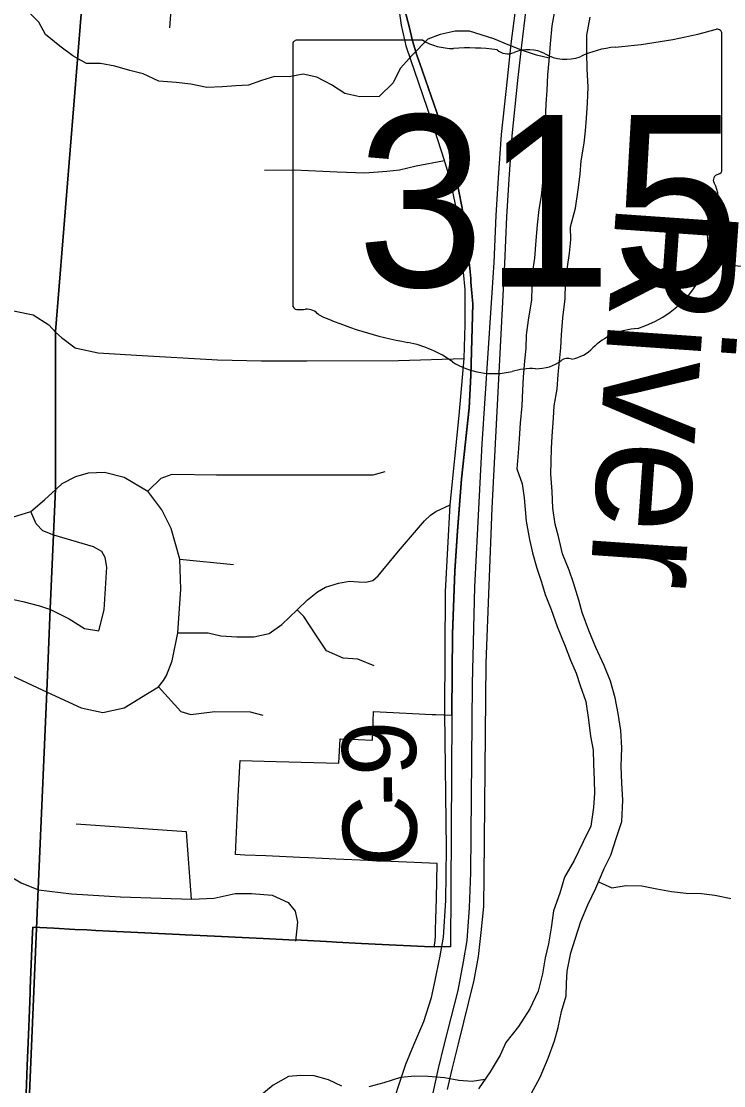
# Model space of a CAD drawing. Extents: x 0 to 34, y 0 to 22.
# Drawn here: x 17.773 to 18.313, y 5.441 to 6.258 of the extents above; entities that cross this region are included whole.
import ezdxf

# ---------------------------------------------------------------- set-up
doc = ezdxf.new("R2010")
doc.units = 0
for name, color, linetype in [('GM_X_City_Street', 7, 'Continuous'), ('GM_X_Corporation', 7, 'Continuous'), ('GM_X_County_Road', 7, 'Continuous'), ('GM_X_County_Road_Text', 7, 'Continuous'), ('GM_X_Major_River', 7, 'Continuous'), ('GM_X_Major_River_Text', 7, 'Continuous'), ('GM_X_Minor_River', 7, 'Continuous'), ('GM_X_State_Location', 7, 'Continuous'), ('GM_X_State_Route', 7, 'Continuous'), ('GM_X_State_Shield', 7, 'Continuous')]:
    doc.layers.add(name, color=color, linetype=linetype)

msp = doc.modelspace()

# ---------------------------------------------------------------- linework, layer by layer
at = {"layer": 'GM_X_City_Street'}
msp.add_line((17.89471, 5.84522), (17.93593, 5.84123), dxfattribs=at)
for points in [[(17.88709, 6.2533), (17.88947, 6.28453), (17.88813, 6.29703), (17.88332, 6.31817)], [(17.95974, 6.14412), (17.98255, 6.14437), (18.01567, 6.14269), (18.03679, 6.14196), (18.05383, 6.14317), (18.06343, 6.14437), (18.07639, 6.14749), (18.09811, 6.15159)], [(18.30145, 6.07219), (18.37497, 6.06686), (18.37576, 6.06678), (18.3924, 6.06505), (18.41174, 6.06059), (18.42842, 6.05801), (18.44511, 6.05278), (18.45076, 6.05245), (18.50915, 6.04895), (18.56071, 6.04583), (18.63152, 6.04155), (18.6683, 6.03945), (18.67549, 6.04139), (18.68078, 6.04406)], [(17.60122, 5.92209), (17.63267, 5.9094), (17.63905, 5.90785), (17.6524, 5.90631), (17.66246, 5.90573), (17.67, 5.90399), (17.68083, 5.9007), (17.69169, 5.89479), (17.72822, 5.87903), (17.7358, 5.87621), (17.75056, 5.87511), (17.76623, 5.87748), (17.78024, 5.88185), (17.79065, 5.89078), (17.79936, 5.8988), (17.80432, 5.90336), (17.81489, 5.90882), (17.82455, 5.91156), (17.83694, 5.9121), (17.85207, 5.90828), (17.87011, 5.89735)], [(17.87011, 5.89735), (17.8805, 5.90755), (17.88888, 5.91046), (17.92278, 5.9101), (18.04323, 5.91004), (18.0525, 5.91255)], [(17.87846, 5.74713), (17.88221, 5.75203), (17.88451, 5.7558), (17.88876, 5.76716), (17.89326, 5.78872), (17.89544, 5.82226), (17.89471, 5.84522), (17.88816, 5.86891), (17.88086, 5.88313), (17.87011, 5.89735)], [(17.83239, 5.79019), (17.83658, 5.8064), (17.83876, 5.83921), (17.83749, 5.8465), (17.83476, 5.85105), (17.82838, 5.8547), (17.79785, 5.86364), (17.78956, 5.86709), (17.78428, 5.87238), (17.78024, 5.88185)], [(17.89326, 5.78872), (17.91658, 5.78872), (17.92623, 5.78631), (17.93844, 5.78551), (17.95161, 5.78552), (17.96328, 5.78818), (17.97301, 5.79515), (17.98477, 5.80625), (17.99293, 5.81405), (18.00043, 5.82009), (18.00671, 5.82372), (18.01662, 5.82686), (18.02509, 5.82831), (18.0321, 5.82783), (18.03766, 5.82759), (18.04298, 5.8288), (18.04709, 5.83243), (18.06281, 5.85128), (18.08264, 5.87473), (18.08723, 5.87909), (18.09134, 5.88175), (18.10239, 5.88694)], [(17.72511, 5.82348), (17.77407, 5.81278), (17.78682, 5.8095), (17.7954, 5.80658), (17.80979, 5.79929), (17.82145, 5.79201), (17.83239, 5.79019)], [(18.04402, 5.76343), (18.03137, 5.76848), (18.02012, 5.76917), (18.00739, 5.77479), (17.99983, 5.78646), (17.98997, 5.80108), (17.98477, 5.80625)], [(17.53865, 5.74479), (17.57105, 5.7377), (17.60385, 5.73733), (17.67347, 5.73551), (17.68368, 5.73806), (17.69497, 5.74353), (17.70117, 5.75045), (17.71101, 5.75592), (17.72486, 5.76102), (17.73507, 5.7603), (17.74564, 5.75993), (17.76168, 5.75774), (17.79269, 5.74317), (17.8189, 5.73114), (17.83567, 5.7275), (17.85207, 5.73114), (17.86993, 5.74207), (17.87846, 5.74713)], [(17.87846, 5.74713), (17.89544, 5.72822), (17.9031, 5.72603), (17.92169, 5.72822), (17.94866, 5.72786), (17.95848, 5.7253)], [(17.90374, 5.58417), (17.89994, 5.63581), (17.81506, 5.64167)], [(17.74553, 5.62732), (17.75422, 5.61127), (17.76191, 5.60324), (17.77295, 5.59655), (17.78618, 5.5912), (17.81142, 5.58818), (17.84922, 5.58584), (17.90374, 5.58417), (17.92113, 5.58484), (17.93719, 5.58852), (17.9499, 5.58852), (17.96562, 5.58718), (17.97799, 5.5815), (17.98335, 5.57481), (17.98502, 5.56644), (17.98369, 5.55173)]]:
    msp.add_lwpolyline(points, dxfattribs=at)
at = {"layer": 'GM_X_Corporation'}
for points in [[(17.86713, 7.43753), (17.84464, 6.9681), (17.84153, 6.90332), (17.83979, 6.78846), (17.83713, 6.72644), (17.83385, 6.6616), (17.83316, 6.64799), (17.8259, 6.57705), (17.82174, 6.29892), (17.79921, 6.02002), (17.79914, 5.89934), (17.79763, 5.86418), (17.79518, 5.80711), (17.79247, 5.7437), (17.78596, 5.59174), (17.77304, 5.29021)], [(17.77304, 5.29021), (17.78596, 5.59174), (17.79247, 5.7437), (17.79518, 5.80711), (17.79763, 5.86418), (17.79914, 5.89934), (17.79921, 6.02002), (17.82174, 6.29892), (17.8259, 6.57705), (17.83316, 6.64799), (17.83385, 6.6616), (17.83713, 6.72644), (17.83979, 6.78846), (17.84153, 6.90332), (17.84464, 6.9681), (17.86713, 7.43753)], [(18.06767, 6.26697), (18.07089, 6.25443), (18.07359, 6.24337), (18.07687, 6.23247), (18.08075, 6.22174), (18.08154, 6.21946), (18.09432, 6.18256), (18.09979, 6.16497), (18.10465, 6.1472), (18.10891, 6.12928), (18.11161, 6.11491), (18.11341, 6.10332), (18.11488, 6.09466), (18.11522, 6.09139), (18.11597, 6.08435), (18.1168, 6.07571), (18.11748, 6.06851), (18.11798, 6.06339), (18.11822, 6.06073), (18.11826, 6.05797), (18.11995, 6.04101), (18.11829, 5.9863), (18.117, 5.96124), (18.11123, 5.90661), (18.10801, 5.86677), (18.10609, 5.83593), (18.10416, 5.78773), (18.10381, 5.7272), (18.10377, 5.72482), (18.10276, 5.54747), (18.09011, 5.54734), (18.08282, 5.54771), (18.05006, 5.54935), (18.03434, 5.55013), (18.0152, 5.55109), (18.01141, 5.55128), (18.00738, 5.55148), (17.98792, 5.55245), (17.97836, 5.55283), (17.95876, 5.55379), (17.94266, 5.55458), (17.9267, 5.55537), (17.91042, 5.55616), (17.89872, 5.55674), (17.89456, 5.55694), (17.87845, 5.55773), (17.86236, 5.55852), (17.84612, 5.55932), (17.83026, 5.5601), (17.82316, 5.56045), (17.81407, 5.56089), (17.79797, 5.56168), (17.7817, 5.56248), (17.78153, 5.55851), (17.78006, 5.52177), (17.77978, 5.51485), (17.77969, 5.51249), (17.77914, 5.49889), (17.77838, 5.47994), (17.77742, 5.45629), (17.77656, 5.43486)], [(17.77656, 5.43486), (17.77742, 5.45629), (17.77838, 5.47994), (17.77914, 5.49889), (17.77969, 5.51249), (17.77978, 5.51485), (17.78006, 5.52177), (17.78153, 5.55851), (17.7817, 5.56248), (17.79797, 5.56168), (17.81407, 5.56089), (17.82316, 5.56045), (17.83026, 5.5601), (17.84612, 5.55932), (17.86236, 5.55852), (17.87845, 5.55773), (17.89456, 5.55694), (17.89872, 5.55674), (17.91042, 5.55616), (17.9267, 5.55537), (17.94266, 5.55458), (17.95876, 5.55379), (17.97836, 5.55283), (17.98792, 5.55245), (18.00738, 5.55148), (18.01141, 5.55128), (18.0152, 5.55109), (18.03434, 5.55013), (18.05006, 5.54935), (18.08282, 5.54771), (18.09011, 5.54734), (18.0908, 5.55174), (18.09126, 5.55616), (18.09121, 5.5606), (18.09139, 5.56858), (18.09175, 5.57657), (18.09201, 5.58456), (18.09243, 5.61137), (18.03921, 5.61374), (18.01453, 5.61484), (17.99351, 5.61578), (17.98698, 5.61607), (17.9608, 5.61723), (17.94461, 5.61796), (17.93741, 5.61828), (17.93942, 5.65772), (17.93993, 5.66775), (17.9411, 5.69061), (17.9688, 5.68983), (18.0169, 5.6885), (18.01795, 5.70729), (18.03164, 5.70674), (18.04267, 5.7063), (18.04322, 5.72059), (18.04352, 5.72827), (18.08865, 5.72604), (18.09132, 5.7259), (18.10378, 5.72548), (18.10381, 5.72744), (18.10416, 5.78798), (18.10608, 5.83618), (18.10801, 5.86702), (18.11122, 5.90686), (18.117, 5.96148), (18.11829, 5.98655), (18.11995, 6.04126), (18.11826, 6.05797), (18.11822, 6.06073), (18.11798, 6.06339), (18.11748, 6.06851), (18.1168, 6.07571), (18.11597, 6.08435), (18.11522, 6.09139), (18.11488, 6.09466), (18.11341, 6.10332), (18.11325, 6.10333), (18.11161, 6.11491), (18.10891, 6.12928), (18.10465, 6.1472), (18.09979, 6.16497), (18.09432, 6.18256), (18.08154, 6.21946), (18.08075, 6.22174), (18.07687, 6.23247), (18.07359, 6.24337), (18.07089, 6.25443), (18.06767, 6.26697)]]:
    msp.add_lwpolyline(points, dxfattribs=at)
at = {"layer": 'GM_X_County_Road'}
for points in [[(18.09838, 5.72792), (18.09884, 5.82033), (18.10239, 5.88694), (18.10923, 5.9555), (18.1131, 5.99926), (18.11407, 6.02538), (18.11383, 6.05246), (18.11141, 6.07905), (18.10682, 6.11629), (18.10295, 6.13515), (18.09811, 6.15159), (18.08816, 6.18254), (18.06896, 6.23849), (18.06499, 6.25532), (18.06238, 6.27318), (18.0612, 6.29223), (18.06366, 6.31826)], [(17.66577, 6.0394), (17.70033, 6.0385), (17.71867, 6.03753), (17.74098, 6.03692), (17.76814, 6.03573), (17.78207, 6.03295), (17.79409, 6.02537), (17.79943, 6.01948), (17.80391, 6.01552), (17.81439, 6.00757), (17.81531, 6.00738)], [(17.81531, 6.00738), (17.83194, 6.00384), (17.86138, 6.00197), (17.92363, 5.99827), (17.95739, 5.99755), (17.95933, 5.99755)], [(17.95933, 5.99755), (17.99224, 5.99749), (18.06274, 5.99779), (18.1131, 5.99926)], [(18.0943, 5.53805), (18.09449, 5.53901), (18.09731, 5.55495), (18.09908, 5.58313), (18.09956, 5.62303), (18.09837, 5.72693), (18.09838, 5.72792)], [(18.03934, 5.15761), (18.05195, 5.1735), (18.0613, 5.18628), (18.06838, 5.20157), (18.07226, 5.21367), (18.0734, 5.22075), (18.07431, 5.22919), (18.07385, 5.24403), (18.06518, 5.28603), (18.05879, 5.31547), (18.05462, 5.33305), (18.05334, 5.34634), (18.05206, 5.37523), (18.05385, 5.39312), (18.05641, 5.41306), (18.06178, 5.43735), (18.06842, 5.45729), (18.07456, 5.47212), (18.08223, 5.49001), (18.08811, 5.50842), (18.09092, 5.52171), (18.0943, 5.53805)]]:
    msp.add_lwpolyline(points, dxfattribs=at)
at = {"layer": 'GM_X_Major_River'}
for points in [[(18.18279, 6.26772), (18.18064, 6.25486), (18.17923, 6.24122), (18.17821, 6.22796), (18.17723, 6.21735), (18.17661, 6.20521), (18.17603, 6.19497), (18.17538, 6.18132), (18.17511, 6.16804), (18.17362, 6.15023), (18.17331, 6.13467), (18.17234, 6.12444), (18.17062, 6.11385), (18.16924, 6.10211), (18.16824, 6.08998), (18.16721, 6.07634), (18.16546, 6.0646), (18.16505, 6.04411), (18.16251, 6.0305), (18.16073, 6.01763), (18.16052, 6.00701), (18.15957, 5.99753), (18.15856, 5.98503), (18.15799, 5.97517), (18.15737, 5.96303), (18.15634, 5.94977), (18.15534, 5.93764), (18.15475, 5.92703), (18.15374, 5.91452), (18.15768, 5.90306), (18.15936, 5.89239), (18.1609, 5.87452), (18.16328, 5.86043), (18.16572, 5.85014), (18.1689, 5.83831), (18.17248, 5.82761), (18.17532, 5.81807), (18.18002, 5.80659), (18.18468, 5.79359), (18.19083, 5.77829), (18.19478, 5.76758), (18.19913, 5.75763), (18.20235, 5.74808), (18.20666, 5.73585), (18.20865, 5.72176), (18.21029, 5.70921), (18.21236, 5.69854), (18.21252, 5.6879), (18.21303, 5.67537), (18.21321, 5.6655), (18.21261, 5.6545), (18.21043, 5.64012), (18.2045, 5.62809), (18.19777, 5.6138), (18.19031, 5.60103), (18.18665, 5.58858), (18.18183, 5.57501), (18.18006, 5.56214), (18.17791, 5.54965), (18.17543, 5.53907), (18.17328, 5.52659), (18.16998, 5.51337), (18.16365, 5.49982), (18.15504, 5.48633), (18.14531, 5.47399), (18.14095, 5.46421), (18.13311, 5.45145), (18.12413, 5.43834)], [(18.16462, 5.43452), (18.1717, 5.44729), (18.17768, 5.46197), (18.18249, 5.47516), (18.18535, 5.48536), (18.18787, 5.49784), (18.19152, 5.50991), (18.19172, 5.5194), (18.19228, 5.52888), (18.19522, 5.54286), (18.19846, 5.55343), (18.2029, 5.567), (18.20809, 5.57981), (18.21441, 5.59259), (18.22078, 5.60765), (18.22591, 5.6178), (18.22995, 5.63063), (18.23439, 5.64383), (18.23509, 5.66014), (18.23422, 5.67306), (18.23372, 5.68635), (18.23438, 5.70039), (18.23351, 5.71369), (18.23149, 5.72663), (18.22908, 5.73883), (18.22555, 5.75142), (18.22086, 5.76366), (18.21431, 5.77745), (18.20889, 5.79046), (18.20385, 5.80422), (18.20139, 5.81376), (18.19711, 5.82713), (18.19389, 5.83668), (18.18883, 5.84931), (18.18569, 5.86265), (18.18322, 5.87219), (18.18119, 5.88438), (18.18069, 5.89729), (18.17982, 5.9106), (18.18022, 5.93033), (18.18079, 5.93981), (18.18182, 5.95345), (18.18239, 5.96293), (18.18454, 5.97579), (18.18552, 5.98716), (18.18745, 6.00762), (18.18802, 6.01748), (18.18905, 6.03074), (18.19085, 6.04513), (18.1911, 6.05727), (18.19248, 6.06977), (18.19421, 6.08037), (18.19517, 6.0906), (18.19499, 6.10047), (18.19869, 6.11482), (18.20086, 6.12882), (18.20225, 6.14094), (18.20321, 6.15117), (18.20538, 6.1648), (18.20632, 6.17427), (18.20728, 6.18412), (18.20788, 6.19549), (18.20851, 6.20801), (18.20765, 6.22169), (18.20752, 6.23422), (18.20741, 6.24788), (18.20996, 6.2615)]]:
    msp.add_lwpolyline(points, dxfattribs=at)
at = {"layer": 'GM_X_Minor_River'}
for points in [[(18.17837, 6.23011), (18.16889, 6.23232), (18.15794, 6.2359), (18.14701, 6.24024), (18.13608, 6.24496), (18.11721, 6.25094), (18.10622, 6.25072), (18.09481, 6.24823), (18.08528, 6.24457), (18.07337, 6.23259), (18.06414, 6.22209), (18.05868, 6.21116), (18.04793, 6.20068), (18.03314, 6.20051), (18.02143, 6.20297), (18.01128, 6.20957), (17.99999, 6.21544), (17.98941, 6.21788), (17.97877, 6.21575), (17.9674, 6.21592), (17.9575, 6.21303), (17.9476, 6.20938), (17.93773, 6.20877), (17.92749, 6.20816), (17.91536, 6.20758), (17.90326, 6.21003), (17.8919, 6.21134), (17.87865, 6.2123), (17.8666, 6.21818), (17.8564, 6.22061), (17.84469, 6.22382), (17.83373, 6.22588), (17.82312, 6.22604), (17.81258, 6.23189), (17.80245, 6.23926), (17.79157, 6.24816), (17.7864, 6.25774), (17.7733, 6.27047)], [(18.21645, 5.59744), (18.22665, 5.59281), (18.23766, 5.59455), (18.24979, 5.59437), (18.26113, 5.59192), (18.27247, 5.58986), (18.28383, 5.58855), (18.29558, 5.58838), (18.30579, 5.58709), (18.31827, 5.58462)], [(18.01916, 5.44049), (18.00899, 5.44521), (17.99804, 5.4484), (17.98781, 5.44856), (17.97833, 5.44794), (17.96649, 5.44127), (17.95614, 5.43269)], [(18.12905, 5.44553), (18.11928, 5.44395), (18.10906, 5.44486), (18.09809, 5.44692), (18.0856, 5.44787), (18.07536, 5.44802), (18.06436, 5.44704), (18.05142, 5.44306), (18.04, 5.43981)]]:
    msp.add_lwpolyline(points, dxfattribs=at)
at = {"layer": 'GM_X_State_Route'}
for points in [[(18.08939, 5.43542), (18.09356, 5.45407), (18.09795, 5.47183), (18.10847, 5.51394), (18.11264, 5.53588), (18.11549, 5.55233), (18.11725, 5.57755), (18.11834, 5.60431), (18.11966, 5.7495), (18.12141, 5.82386), (18.1269, 5.93396), (18.13629, 6.07321), (18.13782, 6.10918), (18.13958, 6.13813), (18.14199, 6.17147), (18.14637, 6.21402), (18.14923, 6.241), (18.15537, 6.28859), (18.15716, 6.30369), (18.16331, 6.35946), (18.16857, 6.40552), (18.17366, 6.45423), (18.17808, 6.48556), (18.18492, 6.53665)], [(18.1406, 5.99834), (18.14444, 6.07225), (18.14598, 6.10822), (18.14773, 6.13717), (18.15015, 6.1705), (18.15453, 6.21305), (18.15738, 6.24003), (18.16071, 6.2677)], [(18.10036, 5.43795), (18.10409, 5.45352), (18.10891, 5.47304), (18.12076, 5.52195), (18.12427, 5.53993), (18.12624, 5.55858), (18.12821, 5.57832), (18.12843, 5.602), (18.13019, 5.76562), (18.13469, 5.88449), (18.1406, 5.99834)]]:
    msp.add_lwpolyline(points, dxfattribs=at)
at = {"layer": 'GM_X_State_Shield'}
for p, q in [((18.31113, 6.14423), (18.31113, 6.24892)), ((17.98155, 6.24052), (17.98155, 6.0404)), ((18.08131, 6.24396), (17.98479, 6.24396)), ((18.3111, 6.14426), (18.31113, 6.14423))]:
    msp.add_line(p, q, dxfattribs=at)
for centre, major_axis, start_param, end_param in [((18.19373, 6.51679), (0.34952, 0), 4.814394, 5.042369), ((18.30748, 6.24935), (0.00367, 0), 6.141152, 7.989035), ((17.98532, 6.24094), (0.00382, 0), 1.712693, 3.28349), ((18.1043, 6.26719), (0.03703, 0), 4.042523, 4.731795), ((18.11658, 6.13161), (0.13295, 0), 1.404758, 1.657858), ((18.14676, 6.24198), (0.01068, 0), 3.836095, 5.185415), ((18.16245, 6.21885), (0.02221, 0), 0.950623, 2.079405), ((18.19112, 6.25057), (0.02672, 0), 4.081561, 5.145723), ((18.23831, 6.18284), (0.07032, 0), 1.699011, 2.107814), ((18.31028, 6.13655), (0.00568, 0), 1.883978, 3.671073), ((18.30722, 6.14383), (0.00393, 0), 5.05454, 6.418171), ((18.27416, 6.12331), (0.03409, 0), 5.934695, 6.695948), ((18.32428, 6.10042), (0.0248, 0), 2.387724, 3.262537), ((18.21331, 6.08711), (0.08742, 0), 5.101752, 6.440018), ((17.98536, 6.03996), (0.00385, 0), 3.00124, 4.508301), ((17.98594, 6.06043), (0.0294, 0), 4.665946, 4.897461), ((17.99196, 6.02885), (0.0106, 0), 0.519207, 1.627899), ((18.12578, 6.20865), (0.2524, 0), 4.195997, 4.488961), ((18.25017, 5.98421), (0.04788, 0), 1.647645, 2.488434), ((18.05053, 5.95049), (0.07897, 0), 0.823519, 1.323587), ((18.18951, 6.021), (0.02824, 0), 4.937069, 5.64225), ((18.13594, 6.02786), (0.05011, 0), 4.026481, 4.996735), ((18.16856, 6.01287), (0.0267, 0), 4.691044, 5.507374), ((18.19271, 5.99349), (0.00752, 0), 1.147584, 2.315152), ((18.1649, 5.95867), (0.04118, 0), 1.495662, 1.94098)]:
    msp.add_ellipse(centre, major_axis=major_axis, ratio=0.8, start_param=start_param, end_param=end_param, dxfattribs=at)

# ---------------------------------------------------------------- texts
at = {"layer": 'GM_X_County_Road_Text'}
for s, rotation, p in [('9', 90.65284, (18.07643, 5.67908)), ('-', 90.63918, (18.07669, 5.65594)), ('C', 90.26214, (18.0769, 5.60921))]:
    msp.add_text(s, height=0.05682, rotation=rotation, dxfattribs=at).set_placement(p)
at = {"layer": 'GM_X_Major_River_Text'}
msp.add_text('River', height=0.09469, rotation=266.0033, dxfattribs=at).set_placement((18.23031, 6.12096))
at = {"layer": 'GM_X_State_Location'}
for s, p in [('s', (18.14264, 6.12715)), ('r', (18.14263, 6.12715))]:
    msp.add_text(s, height=0.000189, dxfattribs=at).set_placement(p)
msp.add_text('315', height=0.000189, rotation=0.00001, dxfattribs=at).set_placement((18.07578, 6.11337))
at = {"layer": 'GM_X_State_Shield'}
msp.add_text('315', height=0.131836, dxfattribs=at).set_placement((18.03068, 6.05451))

doc.saveas('drawing.dxf')
